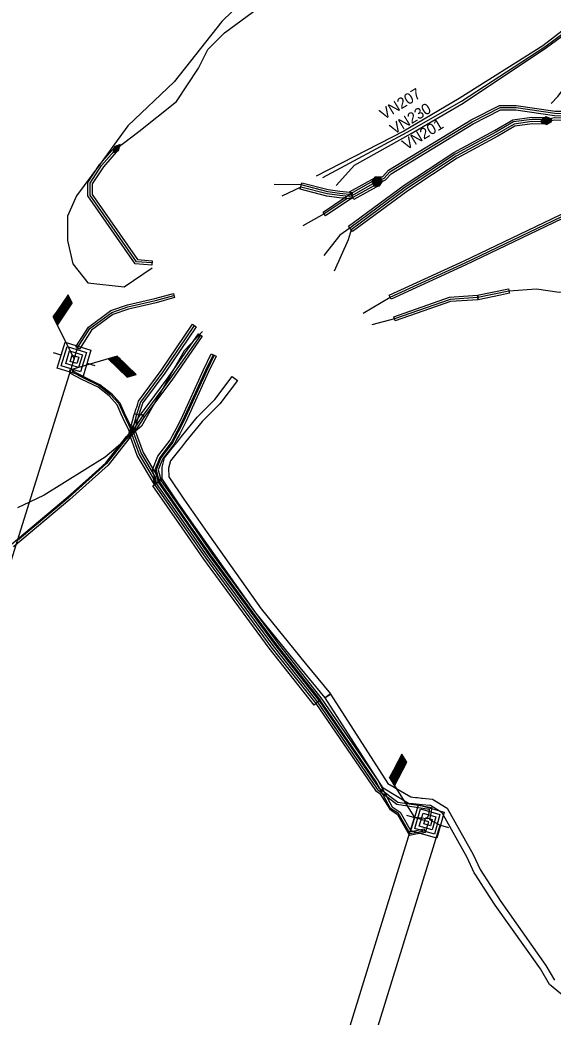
# Model space of a CAD drawing. Extents: x -643811 to -636362, y -1117362 to -1108614.
# Drawn here: x -640949.8 to -640901.3, y -1115995.9 to -1115905.2 of the extents above; entities that cross this region are included whole.
import ezdxf

# ---------------------------------------------------------------- set-up
doc = ezdxf.new("R2010")
doc.units = 0
for name, color, linetype in [('1', 7, 'Continuous'), ('11', 7, 'Continuous'), ('13', 7, 'Continuous'), ('19', 7, 'Continuous'), ('20', 7, 'Continuous'), ('5', 7, 'Continuous'), ('7', 7, 'Continuous'), ('9', 7, 'Continuous')]:
    doc.layers.add(name, color=color, linetype=linetype)

# ---------------------------------------------------------------- blocks, each defined once
blk = doc.blocks.new('VN470')
at = {"layer": '13'}
for points in [[(0, 1.224), (0, 1.972)], [(-1.228, 1.224), (1.228, 1.224)], [(-1.228, -1.233), (-1.228, 1.224)], [(1.228, 1.224), (1.228, -1.233)], [(-0.921, 0.897), (0.921, 0.897)], [(-0.921, -0.945), (-0.921, 0.897)], [(-0.614, 0.61), (0.614, 0.61)], [(-0.614, -0.619), (-0.614, 0.61)], [(-0.307, -0.273), (-0.307, 0.341)], [(-0.307, 0.341), (0.307, 0.341)], [(0.307, 0.341), (0.307, -0.273)], [(0.614, 0.61), (0.614, -0.619)], [(0.921, 0.897), (0.921, -0.945)], [(0.614, -0.619), (-0.614, -0.619)], [(0.307, -0.273), (-0.307, -0.273)], [(1.228, -1.233), (-1.228, -1.233)], [(0.921, -0.945), (-0.921, -0.945)], [(0, -1.233), (0, -1.981)]]:
    blk.add_lwpolyline(points, dxfattribs=at)
blk = doc.blocks.new('VN870')
at = {"layer": '19'}
for points in [[(0, -0.25), (0.5, 0.002), (0, 0.25), (-0.5, 0.002), (0, -0.25)], [(0.37, -0.002), (0, 0.187), (-0.362, 0.002), (0, -0.187), (0.37, -0.002)], [(0.244, -0.002), (0, 0.124), (-0.252, -0.002), (0, -0.124), (0.244, -0.002)], [(0.122, -0.002), (0, 0.061), (-0.13, -0.002), (0, -0.061), (0.122, -0.002)]]:
    blk.add_lwpolyline(points, dxfattribs=at)
blk = doc.blocks.new('VN001')
at = {"layer": '11'}
for p, q in [((2.074, 3.631), (4.49, 3.631)), ((2.103, 3.681), (4.519, 3.681)), ((2.132, 3.731), (2.543, 3.731)), ((1.732, 3.031), (4.144, 3.031)), ((1.76, 3.081), (4.173, 3.081)), ((1.789, 3.131), (4.201, 3.131)), ((1.817, 3.181), (4.23, 3.181)), ((1.846, 3.231), (4.259, 3.231)), ((1.874, 3.281), (4.288, 3.281)), ((1.903, 3.331), (4.317, 3.331)), ((1.932, 3.381), (4.346, 3.381)), ((1.96, 3.431), (4.375, 3.431)), ((1.989, 3.481), (4.403, 3.481)), ((2.017, 3.531), (4.432, 3.531)), ((2.046, 3.581), (4.461, 3.581))]:
    blk.add_line(p, q, dxfattribs=at)
blk.add_lwpolyline([(2.132, 3.732), (0, 0)], dxfattribs=at)
blk.add_lwpolyline([(4.545, 3.727), (2.132, 3.732), (1.705, 2.984), (4.117, 2.985)], close=True, dxfattribs=at)

msp = doc.modelspace()

# ---------------------------------------------------------------- linework, layer by layer
at = {"layer": '1'}
for points in [[(-640962.72, -1115993.27), (-640950.019, -1115952.584), (-640948.927, -1115949.086), (-640944.87, -1115936.09)], [(-642031.663, -1116692.42), (-641919.988, -1116670.681), (-641823.94, -1116652.042), (-641736.648, -1116635.012), (-641632.942, -1116615.129), (-641520.162, -1116593.042), (-641440.652, -1116577.539), (-641345.118, -1116558.759), (-641270.006, -1116544.057), (-641194.685, -1116488.206), (-641128.903, -1116439.373), (-641037.286, -1116371.401), (-640961.13, -1116314.745), (-640955.248, -1116196.6), (-640950.111, -1116094.679), (-640914.416, -1115979.546), (-640914.355, -1115979.348), (-640913.873, -1115977.793)], [(-642031.645, -1116694.863), (-641919.541, -1116673.013), (-641823.481, -1116654.388), (-641736.192, -1116637.368), (-641632.492, -1116617.488), (-641519.71, -1116595.381), (-641440.19, -1116579.885), (-641365.233, -1116564.861), (-641344.662, -1116561.108), (-641269.033, -1116546.285), (-641193.255, -1116490.134), (-641127.476, -1116441.31), (-641035.835, -1116373.328), (-640958.79, -1116315.995), (-640952.852, -1116196.72), (-640947.729, -1116095.101), (-640911.534, -1115978.481)]]:
    msp.add_lwpolyline(points, dxfattribs=at)
at = {"layer": '20'}
for points in [[(-640901.885, -1115914.7), (-640903.172, -1115914.68), (-640904.74, -1115914.899), (-640906.293, -1115915.802), (-640909.986, -1115917.798), (-640914.488, -1115920.766), (-640919.532, -1115924.482), (-640919.888, -1115923.999), (-640914.832, -1115920.274), (-640910.294, -1115917.282), (-640906.587, -1115915.278), (-640904.94, -1115914.321), (-640903.208, -1115914.08), (-640901.875, -1115914.1)], [(-640937.795, -1115927.529), (-640939.31, -1115927.412), (-640943.62, -1115921.243), (-640943.62, -1115920.01), (-640942.53, -1115918.359), (-640941.171, -1115916.799), (-640940.869, -1115917.061), (-640942.21, -1115918.601), (-640943.22, -1115920.13), (-640943.22, -1115921.117), (-640939.09, -1115927.028), (-640937.765, -1115927.13)], [(-640924.146, -1115920.049), (-640921.742, -1115920.665), (-640920.675, -1115920.812), (-640919.779, -1115920.901), (-640919.57, -1115920.921), (-640919.6, -1115921.22), (-640919.6, -1115921.22), (-640919.625, -1115921.477), (-640919.63, -1115921.518), (-640919.68, -1115921.513), (-640920.31, -1115921.451), (-640920.745, -1115921.408), (-640921.858, -1115921.255), (-640924.294, -1115920.631)], [(-640919.779, -1115920.901), (-640919.796, -1115920.871), (-640917.496, -1115919.581), (-640917.104, -1115920.279), (-640919.404, -1115921.569), (-640919.502, -1115921.395), (-640919.6, -1115921.22), (-640919.6, -1115921.22)], [(-640916.174, -1115930.268), (-640909.365, -1115927.139), (-640899.164, -1115922.259), (-640893.234, -1115919.586), (-640891.556, -1115919.745), (-640891.254, -1115921.115), (-640893.188, -1115922.314), (-640894.034, -1115922.562), (-640894.146, -1115922.178), (-640893.352, -1115921.946), (-640891.706, -1115920.925), (-640891.884, -1115920.115), (-640893.166, -1115919.994), (-640898.996, -1115922.621), (-640909.195, -1115927.501), (-640916.006, -1115930.632)], [(-640920.31, -1115921.451), (-640919.711, -1115921.053), (-640919.6, -1115921.22), (-640919.6, -1115921.22), (-640919.489, -1115921.387), (-640919.502, -1115921.395), (-640919.625, -1115921.477), (-640919.68, -1115921.513), (-640921.989, -1115923.047), (-640922.211, -1115922.713)], [(-640908.137, -1115930.281), (-640905.321, -1115929.694), (-640905.25, -1115930.035), (-640905.239, -1115930.086), (-640906.054, -1115930.256), (-640908.069, -1115930.676), (-640908.11, -1115930.48), (-640908.151, -1115930.284)], [(-640935.728, -1115930.493), (-640937.411, -1115930.954), (-640939.914, -1115931.533), (-640941.346, -1115932.029), (-640943.282, -1115933.449), (-640944.392, -1115935.169), (-640944.728, -1115934.952), (-640943.578, -1115933.171), (-640941.534, -1115931.671), (-640940.025, -1115931.148), (-640937.509, -1115930.566), (-640935.832, -1115930.107)], [(-640908.137, -1115930.281), (-640908.123, -1115930.28), (-640908.11, -1115930.48), (-640908.097, -1115930.68), (-640910.6, -1115930.848), (-640915.644, -1115932.609), (-640915.776, -1115932.231), (-640910.68, -1115930.452)], [(-640939.082, -1115940.155), (-640939, -1115939.907), (-640936.953, -1115937.125), (-640934.106, -1115932.918), (-640933.774, -1115933.142), (-640936.627, -1115937.355), (-640938.64, -1115940.093), (-640938.682, -1115940.219), (-640938.804, -1115940.585), (-640938.813, -1115940.611), (-640938.858, -1115940.748), (-640938.998, -1115941.167), (-640939, -1115941.173), (-640939.19, -1115941.11), (-640939.337, -1115941.061), (-640939.38, -1115941.047), (-640939.219, -1115940.564), (-640939.177, -1115940.44)], [(-640938.144, -1115940.215), (-640936.312, -1115937.763), (-640933.534, -1115933.776), (-640933.206, -1115934.004), (-640935.988, -1115937.997), (-640937.642, -1115940.212), (-640938.093, -1115940.815), (-640938.466, -1115941.314), (-640938.47, -1115941.32), (-640938.63, -1115941.2), (-640938.79, -1115941.08), (-640938.594, -1115940.818)], [(-640935.593, -1115942.43), (-640935.14, -1115941.558), (-640933.082, -1115937.044), (-640932.401, -1115935.602), (-640932.13, -1115935.73), (-640932.81, -1115937.17), (-640934.87, -1115941.69), (-640935.395, -1115942.698), (-640935.703, -1115943.289), (-640935.88, -1115943.63), (-640936.99, -1115945.07), (-640937.417, -1115946.152), (-640937.227, -1115946.88), (-640937.227, -1115946.88), (-640937.136, -1115947.228), (-640937.136, -1115947.23), (-640937.136, -1115947.23), (-640937.131, -1115947.247), (-640937.2, -1115947.265), (-640937.228, -1115947.273), (-640937.422, -1115947.323), (-640937.732, -1115946.133), (-640937.706, -1115946.068), (-640937.253, -1115944.92), (-640936.134, -1115943.468), (-640935.901, -1115943.021)], [(-640932.13, -1115935.73), (-640931.949, -1115935.815), (-640932.629, -1115937.254), (-640934.69, -1115941.778), (-640935.262, -1115942.876), (-640935.571, -1115943.47), (-640935.711, -1115943.738), (-640936.814, -1115945.17), (-640937.207, -1115946.165), (-640936.951, -1115947.145), (-640934.312, -1115950.911), (-640932.325, -1115953.767), (-640926.392, -1115961.837), (-640922.308, -1115967.002), (-640917.201, -1115974.442), (-640915.911, -1115976.81), (-640915.2, -1115977.29), (-640914.187, -1115979.038), (-640912.996, -1115978.823), (-640912.96, -1115979.02), (-640914.29, -1115979.26), (-640915.35, -1115977.43), (-640916.063, -1115976.948), (-640917.372, -1115974.547), (-640922.469, -1115967.121), (-640922.473, -1115967.116), (-640926.551, -1115961.959), (-640932.487, -1115953.884), (-640934.476, -1115951.026), (-640937.136, -1115947.23), (-640937.136, -1115947.228), (-640937.227, -1115946.88), (-640937.227, -1115946.88), (-640937.417, -1115946.152), (-640936.99, -1115945.07), (-640935.88, -1115943.63), (-640935.703, -1115943.289), (-640935.395, -1115942.698), (-640934.87, -1115941.69), (-640932.81, -1115937.17)], [(-640944.983, -1115936.996), (-640944.934, -1115937.192), (-640944.022, -1115937.663), (-640944.019, -1115937.665), (-640942.551, -1115938.388), (-640942.537, -1115938.395), (-640942.537, -1115938.395), (-640941.482, -1115939.216), (-640940.74, -1115940.026), (-640940.705, -1115940.065), (-640940.329, -1115940.959), (-640940.083, -1115941.466), (-640939.892, -1115941.859), (-640939.696, -1115942.263), (-640939.638, -1115942.382), (-640939.51, -1115942.646), (-640939.599, -1115942.69), (-640939.6, -1115942.69), (-640939.6, -1115942.69), (-640939.78, -1115942.777), (-640939.788, -1115942.76), (-640939.79, -1115942.757), (-640940.023, -1115942.276), (-640940.214, -1115941.883), (-640940.602, -1115941.082), (-640940.961, -1115940.229), (-640941.686, -1115939.437), (-640942.697, -1115938.65), (-640944.158, -1115937.931), (-640945.192, -1115937.396), (-640945.274, -1115937.068)], [(-640935.084, -1115943.119), (-640933.664, -1115941.349), (-640932.057, -1115939.742), (-640930.479, -1115937.668), (-640930.001, -1115938.032), (-640931.604, -1115940.138), (-640933.216, -1115941.751), (-640934.718, -1115943.622), (-640935.107, -1115944.107), (-640935.236, -1115944.268), (-640936.105, -1115945.347), (-640936.27, -1115945.996), (-640936.261, -1115946.787), (-640934.893, -1115948.82), (-640932.555, -1115952.167), (-640927.841, -1115958.798), (-640923.828, -1115963.74), (-640921.538, -1115966.519), (-640921.77, -1115966.71), (-640922.002, -1115966.901), (-640922.013, -1115966.886), (-640924.292, -1115964.12), (-640928.319, -1115959.162), (-640933.045, -1115952.513), (-640935.387, -1115949.16), (-640936.859, -1115946.973), (-640936.87, -1115945.924), (-640936.655, -1115945.073), (-640935.704, -1115943.892), (-640935.473, -1115943.604)], [(-640939.397, -1115941.112), (-640939.384, -1115941.06), (-640939.347, -1115941.069), (-640939.19, -1115941.11), (-640938.996, -1115941.16), (-640938.998, -1115941.167), (-640939.098, -1115941.553), (-640939.371, -1115942.606), (-640939.406, -1115942.74), (-640939.6, -1115942.69), (-640939.6, -1115942.69), (-640939.708, -1115942.662), (-640939.794, -1115942.64), (-640939.696, -1115942.263)], [(-640939.098, -1115941.553), (-640938.798, -1115941.091), (-640938.63, -1115941.2), (-640938.462, -1115941.309), (-640938.466, -1115941.314), (-640939.31, -1115942.61), (-640939.432, -1115942.799), (-640939.6, -1115942.69), (-640939.6, -1115942.69), (-640939.685, -1115942.635), (-640939.768, -1115942.581), (-640939.638, -1115942.382)], [(-640939.319, -1115942.586), (-640939.31, -1115942.61), (-640938.578, -1115944.591), (-640937.706, -1115946.068), (-640937.227, -1115946.88), (-640937.227, -1115946.88), (-640937.052, -1115947.178), (-640937.136, -1115947.228), (-640937.137, -1115947.228), (-640937.2, -1115947.265), (-640937.31, -1115947.33), (-640937.568, -1115947.482), (-640939.122, -1115944.849), (-640939.745, -1115943.164), (-640939.864, -1115942.842), (-640939.881, -1115942.794), (-640939.794, -1115942.762), (-640939.788, -1115942.76), (-640939.6, -1115942.69), (-640939.6, -1115942.69), (-640939.599, -1115942.69), (-640939.371, -1115942.606)], [(-640937.146, -1115947.215), (-640937.137, -1115947.228), (-640937.136, -1115947.23), (-640934.476, -1115951.026), (-640932.487, -1115953.884), (-640926.551, -1115961.959), (-640922.473, -1115967.116), (-640923.022, -1115967.55), (-640927.108, -1115962.383), (-640933.057, -1115954.291), (-640935.05, -1115951.426), (-640937.719, -1115947.617), (-640937.31, -1115947.33), (-640937.228, -1115947.273)]]:
    msp.add_lwpolyline(points, close=True, dxfattribs=at)
for points in [[(-640950.608, -1115952.946), (-640945.446, -1115948.624), (-640943.569, -1115946.932), (-640941.993, -1115945.511), (-640940.417, -1115943.516), (-640940.117, -1115943.136), (-640939.864, -1115942.842), (-640939.794, -1115942.762), (-640939.79, -1115942.757), (-640939.708, -1115942.662), (-640939.685, -1115942.635), (-640939.676, -1115942.625), (-640939.6, -1115942.69), (-640939.6, -1115942.69), (-640939.449, -1115942.821), (-640939.745, -1115943.164), (-640939.886, -1115943.327), (-640941.774, -1115945.717), (-640945.249, -1115948.851), (-640950.405, -1115953.168)], [(-640900.032, -1115994.231), (-640901.432, -1115993.09), (-640901.581, -1115992.968), (-640902.412, -1115991.553), (-640906.529, -1115985.768), (-640907.052, -1115984.954), (-640908.292, -1115983.025), (-640908.434, -1115982.805), (-640909.077, -1115981.407), (-640911.354, -1115977.364), (-640912.43, -1115976.691), (-640912.479, -1115976.687), (-640913.194, -1115976.615), (-640914, -1115976.534), (-640914.416, -1115976.492), (-640916.734, -1115975.122), (-640922.013, -1115966.886), (-640922.023, -1115966.872), (-640921.77, -1115966.71), (-640921.517, -1115966.548), (-640916.306, -1115974.678), (-640914.224, -1115975.908), (-640914.218, -1115975.909), (-640914.035, -1115975.927), (-640913.792, -1115975.952), (-640913.606, -1115975.97), (-640913.229, -1115976.008), (-640913.163, -1115976.015), (-640912.23, -1115976.109), (-640910.906, -1115976.936), (-640908.543, -1115981.133), (-640907.906, -1115982.515), (-640906.032, -1115985.432), (-640901.908, -1115991.227), (-640901.119, -1115992.572)]]:
    msp.add_lwpolyline(points, dxfattribs=at)
at = {"layer": '5'}
for points in [[(-640941.02, -1115916.93), (-640938.99, -1115915.39), (-640935.56, -1115912.66), (-640933.56, -1115909.62), (-640932.69, -1115907.91), (-640931.18, -1115906.4), (-640919.83, -1115898.04), (-640903.63, -1115885.61), (-640902.03, -1115884.89)], [(-640917.398, -1115919.756), (-640916.775, -1115919.461), (-640916.247, -1115918.903), (-640908.727, -1115914.325), (-640906.139, -1115913.01), (-640904.61, -1115913), (-640901.085, -1115913.521), (-640900.221, -1115913.539), (-640893.805, -1115912.734), (-640888.537, -1115911.924), (-640882.739, -1115911.144), (-640879.066, -1115910.551), (-640877.306, -1115910.519), (-640875.925, -1115911.001), (-640874.611, -1115912.273), (-640873.364, -1115914.153), (-640871.737, -1115916.607), (-640871.461, -1115917.023), (-640867.295, -1115922.811), (-640865.142, -1115925.801), (-640860.163, -1115933.119), (-640856.192, -1115938.541)], [(-640917.3, -1115919.93), (-640916.65, -1115919.62), (-640916.12, -1115919.06), (-640908.63, -1115914.5), (-640906.09, -1115913.21), (-640904.63, -1115913.2), (-640901.108, -1115913.72), (-640900.21, -1115913.74), (-640893.778, -1115912.932), (-640888.509, -1115912.122), (-640882.709, -1115911.342), (-640879.048, -1115910.75), (-640877.338, -1115910.719), (-640876.033, -1115911.176), (-640874.765, -1115912.401), (-640873.581, -1115914.186), (-640871.942, -1115916.658), (-640871.625, -1115917.136), (-640867.508, -1115922.856), (-640865.306, -1115925.915), (-640860.327, -1115933.235), (-640856.356, -1115938.655)], [(-640917.202, -1115920.104), (-640916.525, -1115919.779), (-640915.993, -1115919.217), (-640908.533, -1115914.675), (-640906.041, -1115913.41), (-640904.65, -1115913.4), (-640901.13, -1115913.92), (-640900.2, -1115913.94), (-640893.75, -1115913.13), (-640888.48, -1115912.32), (-640882.68, -1115911.54), (-640879.03, -1115910.95), (-640877.37, -1115910.92), (-640876.14, -1115911.35), (-640874.92, -1115912.53), (-640873.8, -1115914.219), (-640872.148, -1115916.71), (-640871.79, -1115917.25), (-640867.722, -1115922.901), (-640865.47, -1115926.03), (-640860.49, -1115933.35), (-640856.52, -1115938.77)], [(-640901.882, -1115914.5), (-640901.175, -1115914.319), (-640900.179, -1115914.341), (-640893.695, -1115913.526), (-640888.423, -1115912.716), (-640882.621, -1115911.936), (-640878.994, -1115911.349), (-640877.434, -1115911.321), (-640876.355, -1115911.699), (-640875.229, -1115912.787), (-640874.235, -1115914.285), (-640872.558, -1115916.814), (-640872.119, -1115917.477), (-640868.15, -1115922.991), (-640865.798, -1115926.259), (-640860.817, -1115933.581), (-640856.848, -1115938.999)], [(-640901.879, -1115914.3), (-640901.152, -1115914.12), (-640900.19, -1115914.14), (-640893.722, -1115913.328), (-640888.451, -1115912.518), (-640882.651, -1115911.738), (-640879.012, -1115911.15), (-640877.402, -1115911.121), (-640876.247, -1115911.524), (-640875.075, -1115912.659), (-640874.018, -1115914.252), (-640872.354, -1115916.763), (-640871.955, -1115917.364), (-640867.937, -1115922.946), (-640865.634, -1115926.145), (-640860.653, -1115933.465), (-640856.684, -1115938.885)], [(-640901.879, -1115914.3), (-640903.196, -1115914.28), (-640904.873, -1115914.514), (-640906.489, -1115915.453), (-640910.191, -1115917.454), (-640914.717, -1115920.438), (-640919.769, -1115924.16), (-640920.67, -1115924.82), (-640922.14, -1115926.67)], [(-640901.882, -1115914.5), (-640903.184, -1115914.48), (-640904.807, -1115914.706), (-640906.391, -1115915.627), (-640910.089, -1115917.626), (-640914.603, -1115920.602), (-640919.651, -1115924.321), (-640919.92, -1115925.22), (-640921.2, -1115928.08)], [(-640937.78, -1115927.33), (-640939.2, -1115927.22), (-640943.42, -1115921.18), (-640943.42, -1115920.07), (-640942.37, -1115918.48), (-640941.02, -1115916.93)], [(-640917.398, -1115919.756), (-640919.698, -1115921.046), (-640919.79, -1115921.101), (-640920.698, -1115921.011), (-640921.781, -1115920.862), (-640924.195, -1115920.243), (-640926.65, -1115920.2)], [(-640917.3, -1115919.93), (-640919.6, -1115921.22), (-640919.784, -1115921.302), (-640920.722, -1115921.209), (-640921.819, -1115921.058), (-640924.245, -1115920.437), (-640925.96, -1115921.25)], [(-640918.56, -1115931.9), (-640916.09, -1115930.45), (-640909.28, -1115927.32), (-640899.08, -1115922.44), (-640893.2, -1115919.79), (-640891.72, -1115919.93), (-640891.48, -1115921.02), (-640893.27, -1115922.13), (-640894.089, -1115922.37), (-640894.09, -1115922.37)], [(-640917.202, -1115920.104), (-640919.502, -1115921.394), (-640920.033, -1115921.507), (-640922.1, -1115922.88), (-640924.05, -1115923.95)], [(-640890.12, -1115927.63), (-640889.17, -1115927.35), (-640888.873, -1115927.367), (-640888.562, -1115927.384), (-640888.28, -1115927.4), (-640887.9, -1115927.7), (-640887.98, -1115928.52), (-640888.67, -1115929.08), (-640892.21, -1115929.17), (-640894.82, -1115929.61), (-640897.92, -1115929.92), (-640900.7, -1115930.02), (-640902.77, -1115929.71), (-640905.28, -1115929.89), (-640908.11, -1115930.48), (-640910.64, -1115930.65), (-640915.71, -1115932.42), (-640917.77, -1115932.98)], [(-640944.87, -1115936.09), (-640944.56, -1115935.06), (-640944.338, -1115934.716), (-640943.43, -1115933.31), (-640941.44, -1115931.85), (-640939.97, -1115931.34), (-640937.46, -1115930.76), (-640935.78, -1115930.3)], [(-640933.94, -1115933.03), (-640936.79, -1115937.24), (-640938.82, -1115940), (-640939.19, -1115941.11), (-640939.553, -1115942.504), (-640939.529, -1115942.581), (-640939.506, -1115942.655), (-640939.456, -1115942.791), (-640938.759, -1115944.677), (-640937.5, -1115946.812), (-640937.392, -1115947.387), (-640934.722, -1115951.197), (-640932.731, -1115954.058), (-640926.79, -1115962.141), (-640922.711, -1115967.299), (-640917.282, -1115975.207), (-640917.26, -1115975.23), (-640915.48, -1115976.575), (-640912.538, -1115977.025), (-640912.559, -1115977.263), (-640912.724, -1115977.915), (-640913.873, -1115977.793)], [(-640933.37, -1115933.89), (-640936.15, -1115937.88), (-640936.799, -1115938.749), (-640938.63, -1115941.2), (-640939.529, -1115942.581), (-640939.6, -1115942.69), (-640939.675, -1115942.777), (-640940.04, -1115943.2), (-640940.264, -1115943.484), (-640941.92, -1115945.58), (-640945.38, -1115948.7), (-640950.019, -1115952.584)], [(-640932.221, -1115935.687), (-640932.901, -1115937.128), (-640934.96, -1115941.646), (-640935.965, -1115943.576), (-640937.078, -1115945.02), (-640937.522, -1115946.145), (-640937.228, -1115947.273), (-640934.558, -1115951.083), (-640932.569, -1115953.942), (-640926.63, -1115962.019), (-640922.549, -1115967.181), (-640917.127, -1115975.08), (-640915.4, -1115976.385), (-640913.729, -1115976.64), (-640912.322, -1115976.855), (-640912.361, -1115977.297), (-640912.528, -1115977.955), (-640911.534, -1115978.481)], [(-640945.08, -1115937.02), (-640945.02, -1115937.26), (-640944.067, -1115937.752), (-640942.59, -1115938.48), (-640941.55, -1115939.29), (-640940.79, -1115940.12), (-640940.42, -1115941), (-640939.672, -1115942.541), (-640939.694, -1115942.725), (-640939.675, -1115942.777), (-640939.618, -1115942.93), (-640938.941, -1115944.763), (-640937.672, -1115946.913), (-640937.556, -1115947.502), (-640934.886, -1115951.312), (-640932.894, -1115954.175), (-640926.949, -1115962.262), (-640922.872, -1115967.418), (-640917.447, -1115975.32), (-640917.029, -1115975.608), (-640916.133, -1115977.021), (-640915.425, -1115977.5), (-640914.355, -1115979.348), (-640914.341, -1115979.371), (-640913.768, -1115979.268), (-640912.883, -1115979.108), (-640912.585, -1115978.181), (-640913.873, -1115977.793)]]:
    msp.add_lwpolyline(points, dxfattribs=at)
at = {"layer": '9'}
for points in [[(-640922.219, -1115919.551), (-640914.544, -1115915.427), (-640909.611, -1115912.617), (-640902.017, -1115907.692), (-640894.523, -1115902.099), (-640888.732, -1115897.198), (-640825.736, -1115861.357), (-640823.597, -1115860.125), (-640823.294, -1115859.951), (-640818.383, -1115857.123), (-640808.015, -1115851.199), (-640801.43, -1115846.353), (-640790.967, -1115841.544), (-640778.582, -1115834.385), (-640771.684, -1115830.025), (-640765.434, -1115825.232), (-640763.481, -1115824.496), (-640760.331, -1115821.999), (-640747.353, -1115809.446), (-640735.749, -1115797.043), (-640722.214, -1115782.685), (-640717.758, -1115777.524), (-640710.266, -1115769.657), (-640706.07, -1115765.89)], [(-640735.998, -1115796.707), (-640747.797, -1115809.07), (-640760.79, -1115821.637), (-640763.732, -1115823.978), (-640765.874, -1115824.75), (-640771.99, -1115829.763), (-640778.635, -1115833.831), (-640791.209, -1115841.198), (-640801.655, -1115845.755), (-640808.296, -1115850.801), (-640818.522, -1115856.736), (-640823.517, -1115859.534), (-640823.822, -1115859.705), (-640825.968, -1115860.907), (-640889.177, -1115896.76), (-640894.756, -1115901.827), (-640902.205, -1115907.6), (-640909.805, -1115912.381), (-640914.844, -1115915.343), (-640922.832, -1115919.432)], [(-640920.999, -1115920.28), (-640919.333, -1115918.444), (-640914.199, -1115915.559), (-640909.451, -1115912.805), (-640901.855, -1115907.734), (-640894.351, -1115902.222), (-640888.51, -1115897.51), (-640825.443, -1115861.799), (-640823.378, -1115860.536), (-640823.08, -1115860.354), (-640818.262, -1115857.407), (-640807.918, -1115851.604), (-640801.152, -1115846.731), (-640790.764, -1115841.879), (-640778.271, -1115834.698), (-640771.613, -1115830.331)], [(-640901.307, -1115882.65), (-640905.021, -1115883.305), (-640909.915, -1115885.813), (-640915.842, -1115889.937), (-640920.548, -1115894.824), (-640931.419, -1115905.361), (-640935.75, -1115910.856), (-640939.974, -1115914.862), (-640942.554, -1115918.405), (-640944.669, -1115921.22), (-640945.478, -1115923.074), (-640945.479, -1115925.3), (-640944.998, -1115927.409), (-640943.628, -1115929.13), (-640940.323, -1115929.518), (-640937.76, -1115927.786)], [(-640901.429, -1115912.843), (-640900.819, -1115912.205), (-640898.519, -1115909.164), (-640896.929, -1115907.514), (-640892.175, -1115902.43)], [(-640933.182, -1115933.58), (-640934.863, -1115935.334), (-640936.799, -1115938.749), (-640938.745, -1115942.181), (-640939.456, -1115942.791), (-640939.618, -1115942.93), (-640940.264, -1115943.484), (-640942.037, -1115945.004), (-640947.614, -1115948.47), (-640948.927, -1115949.086), (-640950.03, -1115949.603)]]:
    msp.add_lwpolyline(points, dxfattribs=at)

# ---------------------------------------------------------------- block references
at = {"layer": '11'}
for p, rotation in [((-640944.87, -1115936.09), 56), ((-640945.08, -1115937.02), -44.00000000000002), ((-640913.873, -1115977.793), 62)]:
    msp.add_blockref('VN001', p, dxfattribs=dict(at, rotation=rotation))
at = {"layer": '13'}
for p, rotation in [((-640944.87, -1115936.09), -107.00000000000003), ((-640912.68, -1115978.15), -106.00000000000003)]:
    msp.add_blockref('VN470', p, dxfattribs=dict(at, rotation=rotation))
at = {"layer": '19'}
for p, rotation in [((-640901.881, -1115914.5), 5), ((-640901.878, -1115914.3), 5), ((-640941.02, -1115916.93), -131), ((-640917.356, -1115919.736), -150.00000000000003), ((-640917.3, -1115919.93), -150.00000000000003), ((-640917.202, -1115920.104), -150.00000000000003)]:
    msp.add_blockref('VN870', p, dxfattribs=dict(at, rotation=rotation))

# ---------------------------------------------------------------- texts
at = {"layer": '7'}
for s, rotation, p in [('VN207', 31.33208, (-640916.669, -1115914.337)), ('VN230', 31.33355, (-640915.733, -1115915.686)), ('VN201', 31.33503, (-640914.612, -1115917.104))]:
    msp.add_text(s, height=0.9943, rotation=rotation, dxfattribs=at).set_placement(p)

doc.saveas('drawing.dxf')
